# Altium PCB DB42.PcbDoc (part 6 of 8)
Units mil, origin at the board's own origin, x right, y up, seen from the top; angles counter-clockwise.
Board outline 3236.22 x 4456.69 mil, 8 copper layers (Top Layer, MidLayer1, MidLayer2, GND-Layer5, MidLayer3, VCC, MidLayer4, Bottom Layer), stack 62.194 mil thick; 214 components, 470 nets, 1802 pads, 1663 vias.
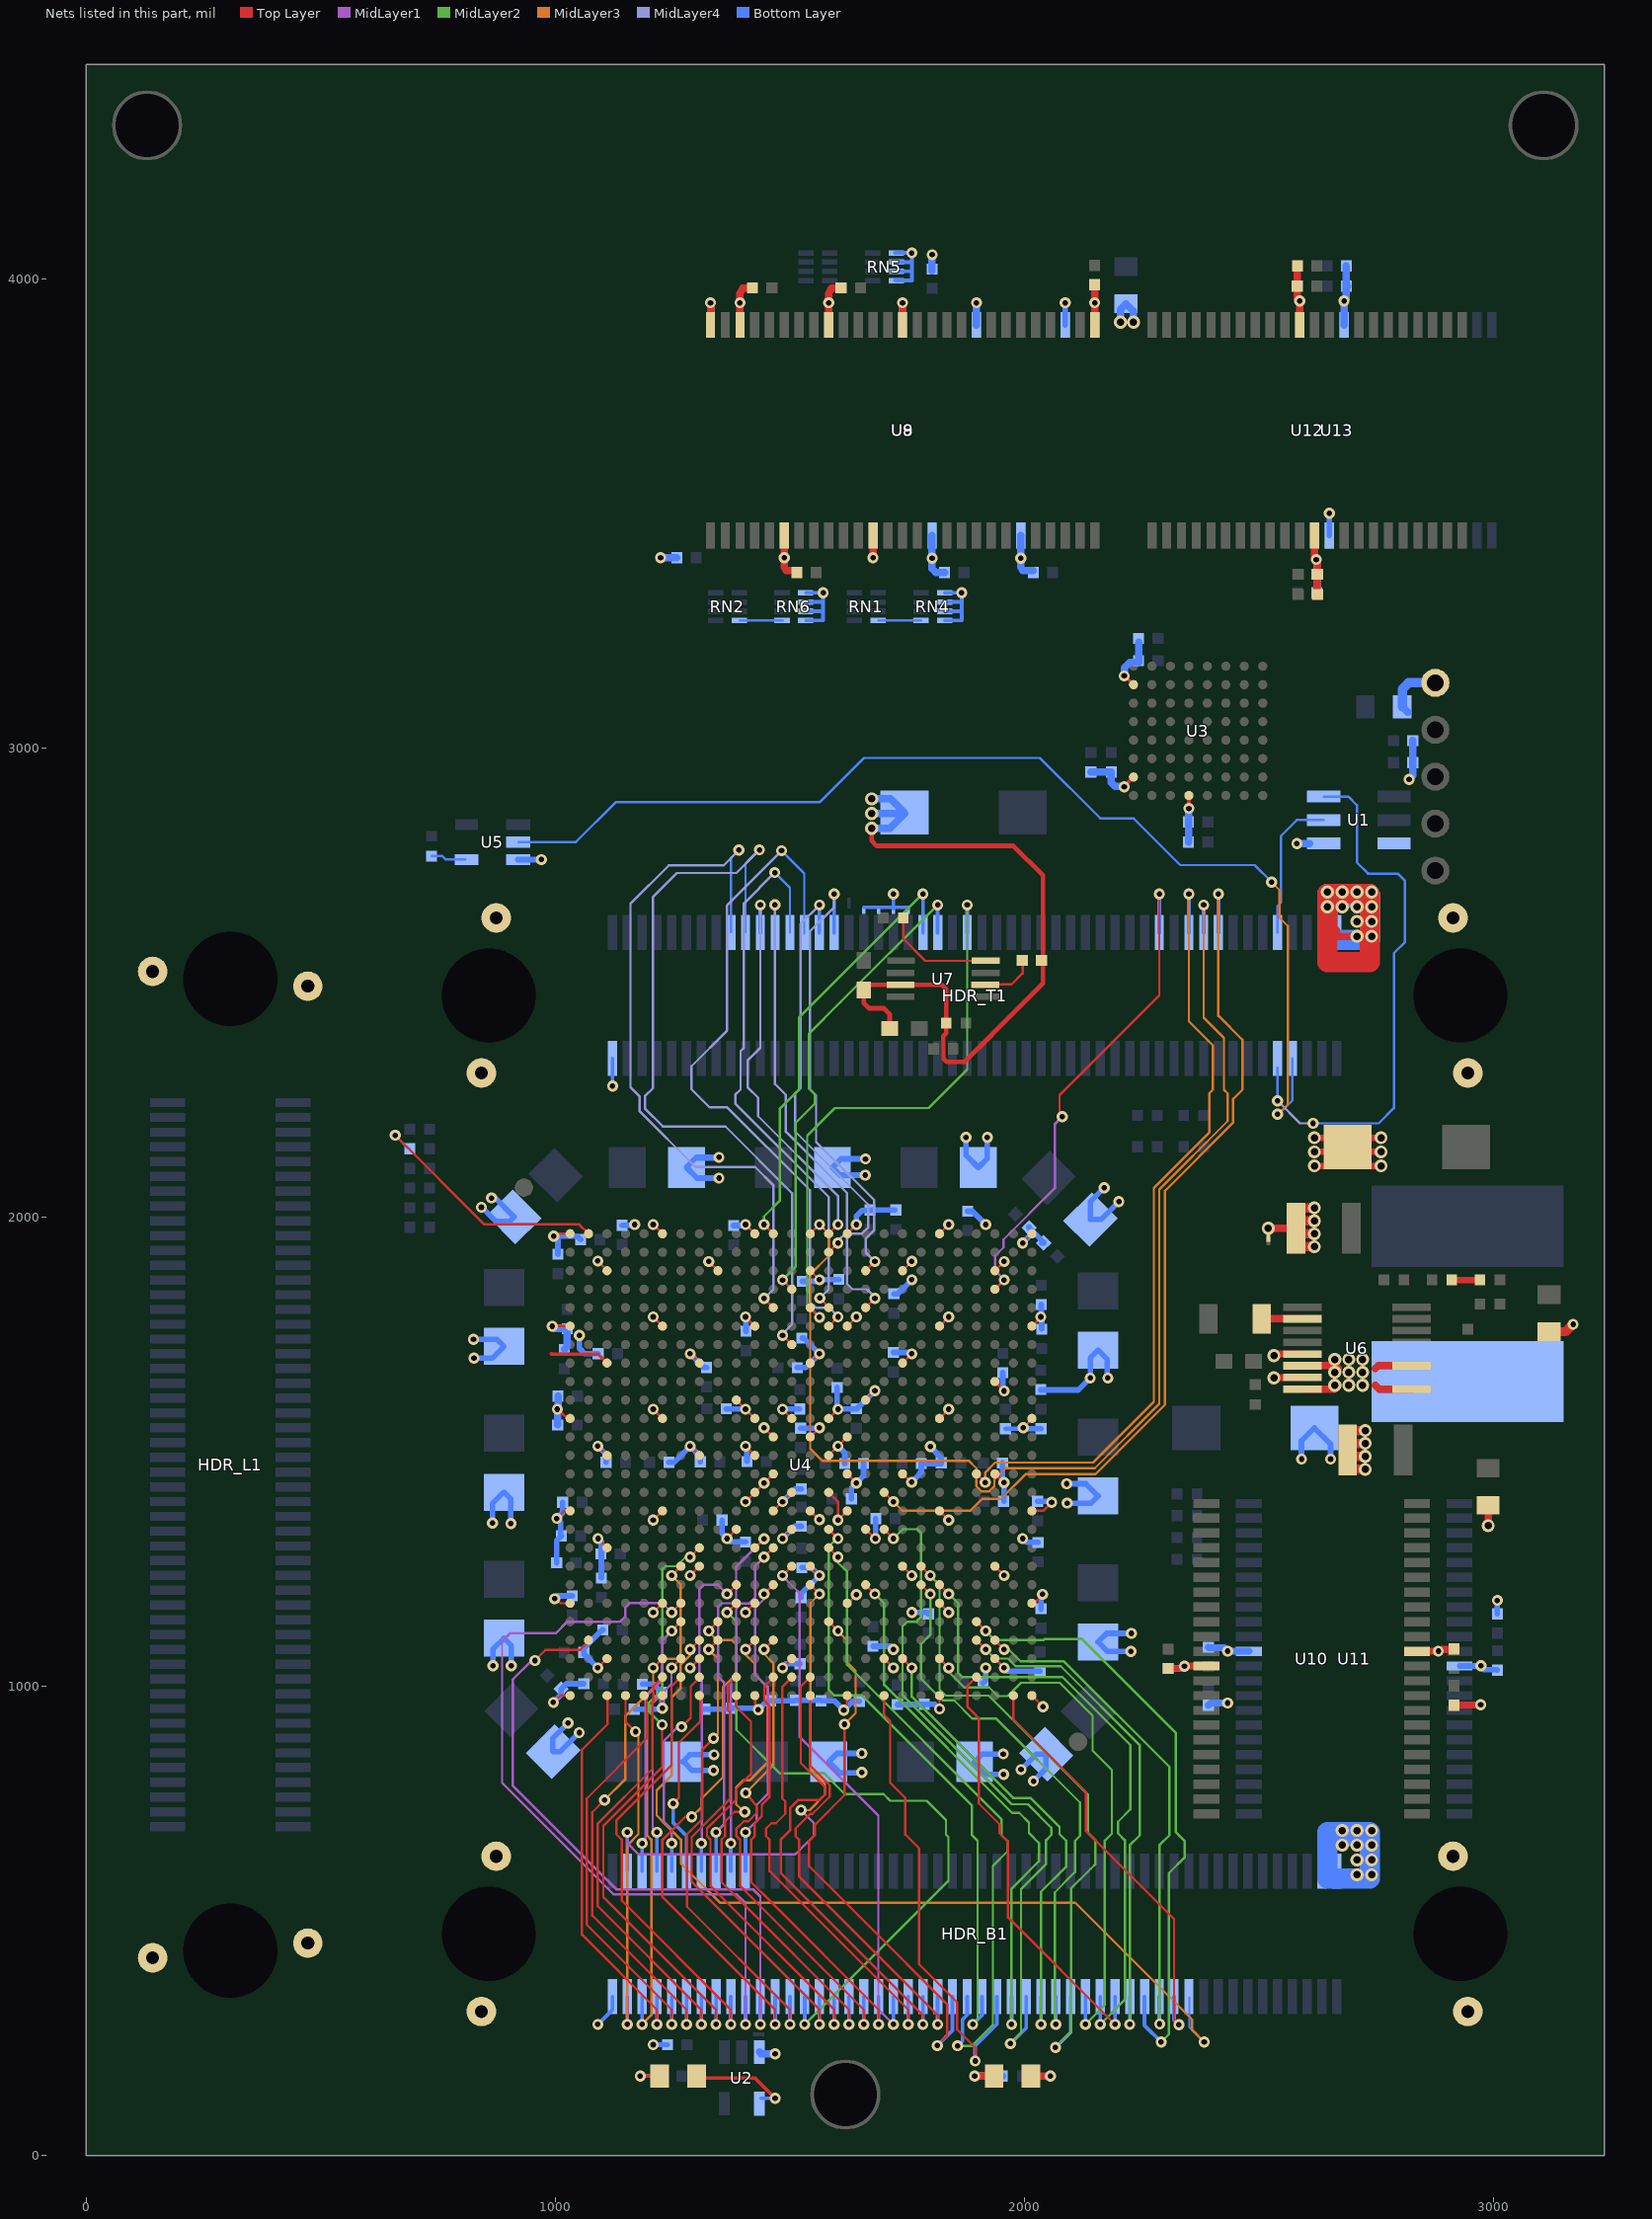
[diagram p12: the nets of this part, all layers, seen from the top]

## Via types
v1: diameter 23.62, hole 11.81, Top Layer to Bottom Layer, 1081 vias
v2: diameter 23.62, hole 11.81, Top Layer to Bottom Layer, tented both sides, 466 vias
v3: diameter 27.56, hole 15.75, Top Layer to Bottom Layer, 116 vias

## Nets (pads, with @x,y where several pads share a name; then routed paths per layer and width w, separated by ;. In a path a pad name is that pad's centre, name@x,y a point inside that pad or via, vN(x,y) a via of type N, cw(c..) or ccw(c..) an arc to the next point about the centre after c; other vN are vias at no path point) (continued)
GND: C1.1 C2.2 C3.2 C4.2 C5.2 C6.2 C7.2 C8.2 C9.2 C10.2 C11.2 C12.2 C13.2 C14.2 C15.2 C16.2 C17.2 C18.2 C19.2 C20.2 C21.2 C22.2 C23.2 C24.2 C25.2 C26.2 C27.2 C28.2 C29.2 C30.2 C31.2 C32.2 C33.2 C34.2 C35.2 C36.2 C37.2 C38.2 C39.2 C40.2 C41.2 C42.2 C43.2 C44.2 C45.2 C46.2 C47.2 C48.2 C49.2 C50.2 C51.2 C52.2 C53.2 C54.2 C55.2 C56.2 C57.2 C58.2 C59.2 C60.2 C61.2 C62.2 C63.2 C64.2 C65.2 C66.2 C67.2 C68.2 C69.2 C70.2 C71.2 C72.2 C73.2 C74.2 C75.2 C76.2 C77.2 C78.2 C79.2 C80.2 C81.2 C82.2 C83.2 C84.2 C85.2 C86.2 C87.2 C88.2 C89.2 C90.2 C91.2 C92.2 C93.2 C94.2 C95.2 C96.2 C97.2 C98.2 C99.2 C100.2 C101.1 C102.2 C103.2 C104.2 C105.2 C106.2 C107.2 C108.2 C109.2 C112.2 C113.2 C114.2 C115.2 C116.2 C118.2 C119.2 C120.2 C121.2 C122.2 C123.2 C124.2 C125.2 C126.2 C127.2 C128.2 C129.2 C130.2 C131.2 C132.2 C133.2 C134.2 C135.2 C136.2 C137.2 C138.2 C139.2 C140.2 C141.2 C142.2 C143.2 C144.2 HDR_B1.1 HDR_B1.98 HDR_B1.100 HDR_B1.MH1 HDR_B1.MH2 HDR_B1.MH3 HDR_B1.MH4 HDR_L1.MH1 HDR_L1.MH2 HDR_L1.MH3 HDR_L1.MH4 HDR_T1.1 HDR_T1.98 HDR_T1.100 HDR_T1.MH1 HDR_T1.MH2 HDR_T1.MH3 HDR_T1.MH4 LED2.2 NT2.2 NT3.2 NT4.2 NT5.2 NT8.2 R25.2 RN4.1 RN4.2 RN4.3 RN4.4 RN5.1 RN5.2 RN5.3 RN5.4 RN6.1 RN6.2 RN6.3 RN6.4 TP1.1 U1.1 U2.3 U3.E8 U3.H2 U3.H7 U4.A1 U4.A6 U4.A11 U4.A16 U4.A21 U4.A26 U4.AA1 U4.AA6 U4.AA11 U4.AA16 U4.AA21 U4.AA26 U4.AD3 U4.AD8 U4.AD13 U4.AD18 U4.AD24 U4.AF1 U4.AF6 U4.AF11 U4.AF16 U4.AF21 U4.AF26 U4.C3 U4.C9 U4.C14 U4.C19 U4.C24 U4.F1 U4.F6 U4.F11 U4.F16 U4.F21 U4.F26 U4.H3 U4.H8 U4.H14 U4.H19 U4.J24 U4.K10 U4.K17 U4.L1 U4.L6 U4.L11 U4.L13 U4.L15 U4.L21 U4.L26 U4.M12 U4.M14 U4.M16 U4.N3 U4.N8 U4.N11 U4.N15 U4.P12 U4.P16 U4.P19 U4.P24 U4.R11 U4.R13 U4.R15 U4.T1 U4.T6 U4.T12 U4.T14 U4.T16 U4.T21 U4.T26 U4.U10 U4.U13 U4.U17 U4.V3 U4.W8 U4.W14 U4.W19 U4.W24 U5.3 U6.13 U6.15 U7.3 U8.6 U8.12 U8.28 U8.41 U8.46 U8.52 U8.54 U9.6 U9.12 U9.28 U9.41 U9.46 U9.52 U9.54 U10.12 U10.34 U11.12 U11.34 U12.12 U12.34 U13.12 U13.34 | length 16704.6
  Top Layer w5: v1(993.19,1767.4) 992.87,1767.72 993.19,1767.72 U4.F1@1031.5,1767.72 ; v1(995.87,965.71) 1011.18,981.02 1031.5,981.02 U4.AF1@1034.8,981.02 ; v1(996.69,1959.45) 1001.81,1964.57 U4.A1@1031.5,1964.57 ; v1@999.29,1189.13 1000.24,1188.18 1011.26,1177.17 U4.AA1@1031.5,1177.17 ; v1(1003.15,1357.87) 1019.29,1374.02 U4.T1@1031.5,1374.02 ; v1(1004.33,1590.55) 1025.31,1571.85 1025.31,1570.87 1025.31,1569.88 U4.L1@1026.3,1570.87 ; v1(1090.55,1039.37) U4.AD3@1110.24,1059.05 ; v1(1090.55,1511.81) U4.N3@1110.24,1492.13 ; v1(1090.59,1906.57) U4.C3@1110.24,1885.83 ; v1(1090.94,1314.96) 1110.24,1295.67 U4.V3@1110.24,1295.28 ; U4.H3@1108.72,1689.87 U4.H3@1109.11,1689.87 ; v1(1208.66,1157.48) U4.AA6@1228.35,1177.17 ; v1(1208.66,1354.33) U4.T6@1228.35,1374.02 ; v1(1208.66,1590.55) U4.L6@1228.35,1570.87 ; v1(1208.66,1787.4) U4.F6@1228.35,1767.72 ; v1(1208.66,1984.25) U4.A6@1228.35,1964.57 ; v1@1226.77,954.33 U4.AF6@1226.77,979.13 ; v1(1227.87,953.54) U4.AF6@1227.87,977.91 ; v1(1287.4,1039.37) U4.AD8@1307.09,1059.05 ; v1(1287.4,1236.22) U4.W8@1307.09,1255.91 ; v1(1287.4,1511.81) U4.N8@1307.09,1492.13 ; v1(1287.4,1708.66) U4.H8@1307.09,1688.98 ; v1(1326.77,1905.51) U4.C9@1346.46,1885.83 ; v1(1366.14,1314.96) U4.U10@1385.83,1334.65 ; U4.K10@1386.61,1610.63 1386.61,1610.24 1386.61,1609.45 v1(1405.51,1590.55) U4.L11@1425.2,1570.87 ; v1(1405.51,1157.48) U4.AA11@1425.2,1177.17 ; v1(1405.51,1393.7) U4.R11@1425.2,1413.39 v1(1444.88,1433.07) U4.P12@1464.57,1452.76 ; v1(1405.51,1511.81) U4.N11@1425.2,1492.13 ; v1(1405.51,1787.4) U4.F11@1425.2,1767.72 ; v1(1405.51,1984.25) U4.A11@1425.2,1964.57 ; U4.AF11@1425.91,979.96 1425.91,957.17 v1(1432.64,950.43) ; v1(1444.88,1551.18) U4.M12@1464.57,1531.5 ; U4.T12@1464.57,1374.02 v1(1484.25,1393.7) U4.R13@1503.94,1413.39 ; v1(1484.25,1039.37) U4.AD13@1503.94,1059.05 ; v1(1484.25,1314.96) U4.U13@1503.94,1334.65 1504.33,1335.04 U4.U13@1505.12,1335.04 ; v1(1484.25,1590.55) U4.L13@1503.94,1570.87 ; U4.W14@1543.31,1255.91 v1(1562.99,1236.22) ; U4.T14@1543.31,1374.02 1562.4,1354.92 v1@1562.99,1354.33 ; U4.M14@1543.31,1531.5 v1(1562.99,1551.18) ; U4.H14@1543.31,1688.98 v1(1562.99,1708.66) ; U4.C14@1543.31,1885.83 1543.7,1885.83 v1(1562.99,1866.54) ; U4.L15@1577.01,1569.88 U4.L15@1580.33,1573.21 ; U4.R15@1582.68,1413.39 1602.36,1393.7 v1(1602.36,1354.33) U4.T16@1622.05,1374.02 ; U4.N15@1582.68,1492.13 v1(1602.36,1511.81) U4.M16@1622.05,1531.5 ; U4.L15@1582.68,1570.87 v1(1602.36,1590.55) ; v1(1614.84,949.37) 1622.05,956.57 U4.AF16@1622.05,980.31 ; U4.AA16@1622.05,1177.17 1623.62,1177.16 v1(1641.73,1195.28) ; U4.P16@1622.05,1452.76 v1(1641.73,1433.07) ; U4.F16@1622.05,1767.72 v1(1641.73,1787.4) ; U4.A16@1622.05,1964.57 v1(1641.73,1984.25) ; U4.U17@1661.42,1334.65 v1(1682.28,1314.96) ; U4.K17@1661.42,1610.24 v1(1681.1,1629.92) ; U4.AD18@1700.79,1059.05 v1(1720.47,1039.37) ; U4.W19@1740.16,1255.91 v1(1759.84,1236.22) ; U4.P19@1740.16,1452.76 v1(1759.45,1435.04) ; U4.H19@1740.16,1688.98 v1(1759.84,1708.66) ; U4.C19@1740.16,1885.83 v1(1759.84,1905.91) ; U4.AF21@1818.9,980.31 1818.9,951.93 v1(1819.09,951.73) ; U4.AA21@1818.9,1177.17 v1(1838.58,1157.48) ; U4.T21@1818.9,1374.02 v1(1838.58,1354.33) ; U4.L21@1818.9,1570.87 v1(1838.58,1590.55) ; U4.F21@1818.9,1767.72 v1(1838.58,1787.4) ; U4.A21@1818.9,1964.57 v1(1838.58,1984.25) ; U4.AD24@1937.01,1059.05 v1(1956.69,1039.37) ; U4.W24@1937.01,1255.91 v1(1956.69,1236.22) ; U4.P24@1937.01,1452.76 1956.1,1434.05 v1@1956.3,1433.86 ; U4.J24@1937.01,1649.61 1937.01,1649.21 v1(1956.69,1629.53) ; U4.C24@1937.01,1885.83 v1(1956.69,1905.51) ; v1@1997.19,1946.36 2015.39,1964.57 U4.A26@2015.75,1964.57 U4.A26@2016.54,1964.57 ; v1(1997.24,1551.18) 2015.75,1569.69 U4.L26@2015.75,1570.87 ; U4.AF26@2015.75,980.31 v1(2039.41,956.65) ; U4.AA26@2015.75,1177.17 2020.47,1177.17 v1@2037.8,1194.49 ; U4.T26@2015.75,1374.02 2039.76,1374.02 v1(2057.87,1392.13) ; U4.F26@2015.75,1767.72 2016.14,1767.72 v1@2032.68,1784.25
  Top Layer w7.87: v1@2212.6,2918.31 U3.H7@2232.28,2937.99 ; v1@2212.6,3154.53 2213.09,3154.04 U3.H2@2232.28,3134.84 ; v1(2350.4,2871.07) U3.E8@2350.39,2898.62
  Top Layer w8: 992.13,1708.66 992.97,1707.82 1091.39,1707.82 U4.H3@1110.24,1688.98 ; 1826.77,2377.95 1827.63,2377.09 1827.63,2337.72 1830.71,2334.65 ; 1875.2,2331.89 1930.31,2387
  Top Layer w10: C119.2@1657.48,2484.25 1657.48,2456.7 1669.29,2444.88 1700.79,2444.88 1712.59,2433.07 C118.2@1712.59,2409.44 ; C119.2@1657.48,2495.07 U7.3@1736.22,2495.07 1823.82,2495.07 1833.15,2485.75 R25.2@1833.15,2413.38 1833.15,2392.2 1826.77,2385.83 1826.77,2377.95 ; v3(1674.21,2828.74) 1674.21,2802.16 1685.04,2791.33 1976.37,2791.33 2039.37,2728.34 2039.37,2547.24 2039.37,2498.03 2016.63,2475.29 ; 1828.68,2336.67 1834.25,2331.1 1872.44,2331.1 2036.41,2495.07
  Top Layer w12: C130.2@2306.5,1038.11 2336.11,1038.11 v1(2341,1043)
  Top Layer w13.78: v3(2618.11,2109.29) C99.2@2669.08,2109.29 ; v3(2618.11,2139.29) C99.2@2669.08,2139.29 ; v3(2618.11,2169.29) C99.2@2669.08,2169.29 ; C99.2@2709.01,2109.29 v3(2759.99,2109.29) ; C99.2@2709.01,2139.29 v3(2759.99,2139.29) ; C99.2@2709.01,2169.29 v3(2759.99,2169.29)
  Top Layer w15: v1@2341,1041.79 v1(2341,1043) 2341.3,1043.3 U10.34@2387.89,1043.3 ; v3(2531.5,1657.48) 2532.26,1658.25 U6.15@2591.08,1658.25 ; v3(2531.5,1704.72) 2535.43,1708.66 U6.13@2590.55,1708.66 ; U10.12@2836.71,1074.8 2881.8,1074.8 v1(2882,1075) 2886.02,1075 2889.76,1078.74 2914.47,1078.74 C129.2@2915.44,1079.71 ; C131.2@2915.31,957.92 2917.32,957.76 C131.2@2915.44,959.64 2914.45,960.63 2915.44,960.63 v1(2972.44,960.63)
  Top Layer w15.75: U8.54@1330.71,3901.57 v2(1330.71,3948.82) ; U8.52@1393.7,3901.57 v2(1393.7,3948.82) ; v2@1393.7,3944.88 v2(1393.7,3948.82) ; 1393.7,3964.57 v2(1393.7,3948.82) ; 1393.7,3968.51 1399.61,3980.32 C125.2@1416.34,3980.32 ; C125.2@1418.31,3978.34 C125.2@1416.34,3980.32 ; C125.2@1420.27,3980.31 C125.2@1416.34,3980.32 ; U8.6@1488.19,3452.76 1488.19,3409.45 v2(1488.19,3405.51) 1488.19,3385.83 1492.13,3377.95 C122.2@1514.76,3377.95 ; U8.46@1582.68,3901.57 v2(1582.68,3948.82) ; v2@1582.68,3944.88 v2(1582.68,3948.82) ; C126.2@1609.25,3980.31 1588.58,3980.32 1582.68,3968.51 1582.68,3964.57 v2(1582.68,3948.82) ; v2(1677.17,3405.51) U8.12@1677.17,3452.76 ; U8.41@1740.16,3901.57 v2(1740.16,3948.82) ; LED2.2@2011.81,169.29 LED2.2@2013.78,169.29 v1(2055.12,169.29) ; U8.28@2149.61,3901.57 v2(2149.61,3948.82) C121.2@2149.6,3987.2 ; v3(2519.68,1976.38) 2578.74,1976.38 C116.2@2582.67,1976.38 ; C138.2@2580.43,4028.54 C138.2@2580.57,4028.67 ; C138.2@2581.69,4027.55 2581.69,3984.24 2581.69,3957.68 v2(2586.61,3952.76) U12.34@2586.61,3901.57 ; U12.12@2618.11,3452.76 2618.11,3405.51 v2(2622.05,3401.57) 2624.72,3398.9 C141.2@2624.72,3370.07 C141.2@2625.71,3371.06 ; C137.2@2623.74,3329.72 2623.74,3370.07 C141.2@2623.77,3370.23 ; 2645.67,2598.43 v3(2708.66,2598.43) ; v3(2988.19,1342.52) C113.2@2988.18,1385.82
  Top Layer w19.68: C115.2@3118.1,1755.9 3153.54,1755.9 v1(3169.29,1771.65)
  Top Layer w20: C116.2@2578.74,1937 v3(2618.1,1937) ; C116.2@2578.74,1964.56 v3(2618.1,1964.56) ; C116.2@2578.74,1992.12 v3(2618.1,1992.12) ; C116.2@2578.74,2019.68 v3(2618.1,2019.68) ; C114.2@2687.01,1462.59 2688.97,1462.59 v3(2726.38,1462.59) ; C114.2@2687.01,1490.15 2688.97,1490.15 v3(2726.38,1490.15) ; C114.2@2687.01,1517.71 2688.97,1517.71 v3(2726.38,1517.71) ; C114.2@2687.01,1545.27 2688.97,1545.27 v3(2726.38,1545.27)
  Top Layer w39.37: 2645.67,2606.3 2653.54,2606.3
  Top Layer w43.31: 2645.67,2543.31 2736.22,2543.31 2736.22,2598.43 2736.22,2629.92 2736.22,2661.42 2736.22,2688.98 2708.66,2688.98 2677.17,2688.98 2645.67,2688.98 v3(2645.67,2661.42) 2645.67,2606.3 2645.67,2598.43 2645.67,2543.31
  Bottom Layer w5: v1@1003.15,1350.39 v1(1003.15,1357.87) ; v1@1223.23,958.66 1227.56,954.33 1228.11,953.78 v1@1228.74,953.15
  Bottom Layer w7.87: v2(1090.55,279.53) 1122.05,311.02 HDR_B1.1@1122.05,338.58 ; v2(1122.05,2279.53) HDR_T1.1@1122.05,2338.58 ; RN6.4@1534.64,3271.65 1570.87,3271.65 1570.87,3291.34 ; RN6.3@1534.64,3291.34 1570.87,3291.34 ; RN6.2@1534.64,3311.02 1570.87,3311.02 ; RN6.1@1534.64,3330.71 v1(1570.87,3330.71) 1570.87,3311.02 ; NT5.2@1657.48,2660.43 1688.97,2660.43 NT3.2@1720.47,2660.43 ; NT3.2@1720.47,2657.48 NT3.2@1720.47,2660.43 ; v2(1720.47,2688.98) NT3.2@1720.47,2660.43 ; RN5.4@1723.62,3996.06 RN5.4@1726.58,3996.06 1759.84,3996.06 1759.84,4015.75 ; RN5.3@1723.62,4015.75 RN5.3@1726.58,4015.75 1759.84,4015.75 ; RN5.2@1723.62,4035.43 RN5.2@1726.58,4035.43 1759.84,4035.43 ; RN5.1@1723.62,4055.12 RN5.1@1726.58,4055.12 v1(1759.84,4055.12) 1759.84,4035.43 ; NT2.2@1751.96,2660.43 NT3.2@1720.47,2660.43 ; RN4.4@1829.93,3271.65 1866.14,3271.65 1866.14,3291.34 ; RN4.3@1829.93,3291.33 1866.14,3291.34 ; RN4.2@1829.93,3311.02 1866.14,3311.02 ; RN4.1@1829.93,3330.7 v1(1866.14,3330.71) 1866.14,3311.02 ; 1570.87,3291.34 1570.87,3311.02 ; 1759.84,4015.75 1759.84,4035.43 ; 1866.14,3291.34 1866.14,3311.02
  Bottom Layer w9.84: v1(1208.66,236.22) C101.1@1239.17,236.22
  Bottom Layer w10: C75.2@1959.65,1549.21 1994.88,1549.21 v1@1996.06,1550.39
  Bottom Layer w11.81: v1(825.58,1739.71) 875.11,1739.71 C10.2@890.44,1724.38 865.43,1699.37 v1(826.56,1699.37) ; v1(865.92,1348.08) 865.92,1389.41 889.95,1413.44 C42.2@890.44,1413.44 891.09,1413.44 905.28,1399.25 v1(905.28,1347.1) ; v1(866.9,1044.02) 866.9,1078.91 C8.2@890.44,1102.45 906.26,1086.63 v1(906.26,1044.02) ; C20.2@994.82,861.98 994.82,889.54 v1(1027.3,922.01) ; C20.2@995.54,860.94 1010.51,860.94 v1(1050.91,901.34) ; v1(1004.33,1590.55) v1@1004.92,1591.14 ; v1(1090.55,1511.81) 1108.27,1494.09 C44.2@1108.27,1477.36 ; v1@1227.56,954.33 C66.2@1227.56,986.61 ; C46.2@1242.13,1477.36 1252.95,1477.36 v1(1287.4,1511.81) 1309.06,1490.16 C30.2@1309.06,1478.35 ; C9.2@1271.74,839.26 C9.2@1272.59,840.11 ; v1(1337.26,820.66) 1292.05,820.66 C9.2@1272.59,840.11 ; v1(1338.24,854.11) 1286.59,854.11 C9.2@1272.59,840.11 ; C71.2@1355.31,1354.33 1355.31,1325.79 v1(1366.14,1314.96) 1373.42,1307.68 C49.2@1405.51,1307.68 ; C77.2@1364.17,1591.54 1404.53,1591.54 v1(1405.51,1590.55) ; v1@1405.12,1512.99 1405.9,1512.21 v1@1406.5,1511.61 ; v1(1405.51,1511.81) 1408.46,1508.86 C17.2@1408.46,1479.33 ; v1(1405.51,1787.4) 1406.5,1786.42 C78.2@1406.5,1756.89 ; v1@1483.07,1039.76 1483.46,1040.16 1491.54,1048.23 C52.2@1521.65,1048.23 ; v1(1484.25,1393.7) v1@1485.24,1394.68 ; C45.2@1515.75,1679.13 1533.46,1679.13 v1(1562.99,1708.66) 1529.53,1742.13 C51.2@1525.59,1742.13 ; C15.2@1522.64,1550.2 1562.01,1550.2 v1(1562.99,1551.18) ; C53.2@1523.62,1188.98 1523.62,1196.85 v1(1562.99,1236.22) 1546.26,1252.95 C27.2@1525.59,1252.95 ; v1@1559.65,1863.19 v1(1562.99,1866.54) v1@1563.58,1867.13 ; v1@1599.41,1508.86 v1(1602.36,1511.81) ; C70.2@1600.39,1636.81 1600.39,1594.09 v1@1602.95,1591.54 ; v1@1601.57,1590.16 1602.17,1590.75 v1@1602.95,1591.54 ; v1@1603.15,1591.34 v1@1602.95,1591.54 ; C12.2@1630.91,1399.61 1630.91,1422.24 v1(1641.73,1433.07) ; v1(1641.73,1984.25) 1641.73,2001.88 1654.1,2014.25 1669.84,2014.25 C96.2@1670.83,2015.24 ; v1(1653.12,816.72) 1652.14,815.74 1606.25,815.74 C39.2@1582.72,839.26 1600.52,857.06 v1(1653.12,857.06) ; v1(1681.1,1629.92) 1642.72,1591.54 C18.2@1641.73,1591.54 v1@1602.95,1591.54 ; v1(1682.28,1314.96) 1683.07,1316.93 C76.2@1683.07,1357.28 ; C86.2@1786.42,961.61 1809.21,961.61 v1(1819.09,951.73) ; v1(1799.61,1511.02) 1822.83,1486.61 C50.2@1822.83,1476.38 ; v1(1875.5,2169.72) 1875.5,2131.76 C5.2@1901.55,2105.71 1920.77,2124.93 v1(1920.77,2169.72) ; v1(1954.72,855.91) 1910.31,855.91 C7.2@1893.67,839.26 1920.34,812.6 v1(1955.51,812.6) ; v1@1955.82,1432.98 1956.6,1432.19 1956.6,1394.33 C28.2@1956.6,1393.97 ; v1(1956.3,1434.25) v1@1958.07,1436.02 ; v1(1992.6,822.62) 2025.35,855.37 C19.2@2046.14,855.37 2046.14,825 v1(2019.17,798.02) ; v1@1998.03,1549.61 1998.42,1549.21 C67.2@2035.43,1549.21 ; v1@2034.25,1788.98 2034.45,1788.78 v1@2034.45,1787.4 ; C89.2@2035.43,1164.37 C89.2@2035.43,1165.35 2035.43,1192.13 v1@2038.58,1195.28 ; v1@2038.19,1197.64 2039.07,1196.75 v1@2042.52,1193.31 ; U9.52@2086.61,3901.57 v2(2086.61,3948.82) ; v1(2090.02,1431.72) 2130.74,1431.72 C40.2@2156.9,1405.56 2141.73,1390.39 v1(2091,1390.39) ; v1(2140.2,1657.06) 2140.2,1699.84 C3.2@2156.88,1716.52 2176.61,1696.79 v1@2176.61,1658.04 ; U9.54@2149.61,3901.57 v2(2149.61,3948.82) ; v1(2169.72,2062.46) 2140.79,2033.53 C21.2@2140.79,1994.88 2163.14,1994.88 v1(2201.21,2032.94) ; v1(2226.79,1074.53) 2176.94,1074.53 C4.2@2156.9,1094.57 2175.23,1112.9 v1(2227.78,1112.9) ; U13.12@2649.61,3452.76 v2(2649.61,3500) ; U11.34@2927.25,1043.3 v1@2972.3,1043.3 ; v1(2973,1044) v1@2972.3,1043.3 ; C136.2@3007.87,1034.44 3006.88,1035.43 2979.33,1035.43 2972.3,1042.47 v1@2972.3,1043.3 ; C134.2@3007.87,1154.52 v1(3007.87,1183.07)
  Bottom Layer w12: v2(842.3,2021.14) 843.29,2021.14 873.79,1990.63 902.21,1990.63 C22.2@912.02,2000.45 871.65,2040.82 v2(863.95,2040.82) ; U5.3@920.04,2762.09 v1(970.22,2762.09) ; v1(995.87,965.71) 1012.39,982.23 C35.2@1012.39,993.98 1024.05,1005.65 C92.2@1060.75,1005.65 ; v1(998.79,1186.73) 1004.68,1192.61 C60.2@1036.15,1192.61 ; C98.2@1002.69,1263.46 1002.69,1310.76 C57.2@1012.8,1320.87 C57.2@1013.51,1320.15 ; C65.2@1005.65,1920.77 1005.65,1950.49 v1(996.69,1959.45) 1046.67,1959.45 C14.2@1053.86,1952.26 ; C57.2@1011.79,1320.29 1011.4,1320.69 1011.4,1320.87 1011.4,1349.63 v1(1003.15,1357.87) 1015.48,1370.21 C69.2@1015.48,1392.36 ; v1(1051.18,1748.03) 1051.18,1720.47 1062.45,1709.21 C94.2@1091.25,1709.21 C94.2@1089.77,1709.21 ; v1(1090.55,1039.37) 1060.76,1069.16 C83.2@1060.76,1072.56 1060.76,1081.21 1099.63,1120.08 C25.2@1101.38,1120.08 ; v1(1090.94,1314.96) 1098.14,1307.76 1098.14,1282.15 C73.2@1098.14,1230.99 ; C63.2@1142.42,1982.77 v1@1166.04,1982.76 ; C32.2@1168.01,951.53 1224.76,951.53 1227.32,954.09 v1@1227.56,954.33 ; C84.2@1185.73,1004.66 1209.51,1004.66 C66.2@1226.97,987.2 C66.2@1227.56,986.61 ; v1(1287.4,1708.66) 1316.37,1679.69 C48.2@1322.5,1679.69 ; C91.2@1318.56,951.52 1372.68,951.52 C90.2@1374.65,953.49 1429.58,953.49 v1(1432.64,950.43) 1451.44,969.23 C47.2@1459.27,969.23 1510.44,969.23 C82.2@1511.42,970.22 1565.54,970.22 C61.2@1566.53,969.23 1594.98,969.23 v1(1614.84,949.37) 1633.72,968.25 C80.2@1648.2,968.25 ; v1(1348.82,2083.07) 1302.26,2083.07 C6.2@1279.61,2105.72 1279.62,2106.39 C6.2@1299.21,2125.98 ; C97.2@1379.92,1982.28 1403.54,1982.28 v1(1405.51,1984.25) ; v1(1484.25,1314.96) 1510.48,1341.19 C16.2@1524.22,1341.19 ; v1(1484.25,1393.7) 1511.44,1420.89 C13.2@1524.22,1420.89 ; v1(1484.25,1590.55) 1484.83,1591.13 C37.2@1520.28,1591.13 ; C79.2@1526.57,1863.19 1559.65,1863.19 v1(1562.99,1866.54) ; v1@1562.99,1866.14 v1(1562.99,1866.54) ; v1(1602.36,1511.81) 1616.72,1497.46 C11.2@1616.72,1475.02 ; C41.2@1603.54,2092.52 1590.58,2105.48 C41.2@1590.58,2105.71 C41.2@1590.75,2105.71 ; C26.2@1604.33,1867.13 v1@1563.58,1867.13 ; v1@1642.3,1433.69 1657.05,1448.44 C29.2@1657.05,1475.02 ; v1@1657.48,2092.52 v1(1660.63,2089.37) 1607.09,2089.37 C41.2@1590.75,2105.71 ; v1(1661.02,2124.02) 1609.06,2124.02 C41.2@1590.75,2105.71 ; C96.2@1671.31,2014.76 C96.2@1670.83,2015.24 C81.2@1723.96,2015.24 ; C33.2@1677.17,1085.63 1713.58,1085.63 v1(1720.47,1078.74) ; C24.2@1720.47,1711.61 1756.89,1711.61 v1(1759.84,1708.66) ; C56.2@1721.46,1836.61 1729.92,1836.61 v1(1759.84,1866.54) ; C95.2@1728.89,961.36 1786.17,961.36 C86.2@1786.42,961.61 ; v1(1759.45,1435.04) 1780.06,1455.65 C23.2@1780.06,1475.02 C50.2@1822.37,1475.02 ; v1(1759.84,1157.48) 1792.32,1157.48 C54.2@1795.28,1154.53 ; C64.2@1878.94,2012.8 1888.78,2012.8 v1(1917.32,1984.25) ; C55.2@1911.42,1006.89 1917.32,1012.8 v1(1917.32,1039.37) ; C43.2@1953.25,1476 1953.25,1437.31 v1(1956.3,1434.25) ; C34.2@1953.74,1668.31 1953.74,1632.48 v1(1956.69,1629.53) ; v1(1956.69,1039.37) 1963.85,1032.21 C93.2@2032.94,1032.21 ; v1(1996.06,1314.96) 2004.27,1306.76 C38.2@2029.01,1306.76 ; v1(1996.06,1944.88) 2015.75,1964.57 ; C31.2@2008.84,1978.33 C31.2@2009.33,1978.82 ; C31.2@2010.17,1977 2040.96,1946.21 C74.2@2040.96,1945.22 C74.2@2037.02,1945.22 ; C88.2@2028.02,1394.33 2055.67,1394.33 v1(2057.87,1392.13) ; C58.2@2033.93,1631.47 2034.91,1631.47 2114.62,1631.47 v1(2140.2,1657.06) ; C87.2@2035.9,1813.51 2035.9,1788.65 v1(2034.65,1787.4) ; C36.2@2036.88,1761.37 2036.88,1785.17 v1(2034.65,1787.4) ; v1@2039.37,1787.4 v1(2034.65,1787.4) ; C132.2@2306.5,1038.11 2336.11,1038.11 v1(2341,1043) ; v1(2590.55,1484.25) 2590.55,1523.43 C112.2@2618.04,1550.91 2652.34,1516.61 v1(2652.34,1484.25) ; C6.2@1299.21,2125.98 1300.79,2127.56 v1(1348.82,2127.56) 1347.24,2125.98 C6.2@1299.21,2125.98 ; v1(1562.99,1866.54) v1@1563.58,1867.13 ; v1(1562.99,1866.54) v1@1563.58,1867.13
  Bottom Layer w15: C133.2@2391.82,959.64 2396.75,964.57 v1(2433.07,964.57) ; C135.2@2391.82,1083.65 2392.8,1082.68 2425.2,1082.68 2432.87,1075 v1(2433,1075) 2433.21,1074.79 U11.12@2478.44,1074.79
  Bottom Layer w15.75: v1(993.19,1767.4) 998.25,1762.34 C85.2@1025.33,1762.34 1025.33,1723.97 C68.2@1019.42,1718.07 ; C62.2@1004.92,1557.09 1004.92,1590.55 1004.92,1592.24 1005.64,1592.97 C72.2@1005.64,1618.68 ; v2(1224.41,3405.51) C123.2@1258.85,3405.51 ; U9.28@1330.71,3901.57 v2@1330.71,3944.88 ; U2.3@1435.04,220.47 1438.97,216.54 v1(1468.5,216.54) ; v3(1674.21,2828.74) 1713.39,2828.74 C100.2@1744.88,2860.24 ; v3(1674.21,2860.24) 1744.17,2860.24 C100.2@1744.88,2860.24 ; v3(1674.21,2891.73) 1713.93,2891.73 1743.68,2861.98 1745.15,2860.51 C100.2@1744.88,2860.24 ; U9.41@1740.16,3901.57 v2(1740.16,3948.82) ; U9.12@1803.15,3452.76 1803.15,3405.51 v2(1803.15,3404.53) 1803.15,3381.89 1811.04,3374.01 C128.2@1829.72,3374.01 ; C124.2@1803.15,4016.72 C124.2@1803.15,4020.66 1803.15,4047.24 v2(1803.15,4051.18) ; U9.46@1897.64,3901.57 v2(1897.64,3948.82) v2@1897.64,3944.88 ; U9.6@1992.13,3452.76 v2(1992.13,3404.53) 1992.13,3385.83 1996.06,3377.95 C127.2@2018.7,3377.95 ; C107.2@2141.73,2948.82 C104.2@2185.04,2948.82 2185.04,2926.19 2192.92,2918.31 v1@2212.6,2918.31 ; v3(2204.72,3907.48) 2204.72,3935.04 C109.2@2216.53,3946.84 2232.28,3931.1 v3(2232.28,3907.48) ; v1(2212.6,3153.54) 2212.6,3170.28 2224.41,3182.09 2243.1,3182.09 C106.2@2243.11,3186.02 C103.2@2243.11,3225.39 ; C102.2@2349.41,2799.21 2350.4,2800.2 2350.4,2842.52 v1(2350.4,2871.07) ; v2(2580.71,2796.26) 2608.06,2796.26 U1.1@2608.25,2796.45 ; v2(2622.05,3401.57) 2623.03,3400.6 C143.2@2623.03,3370.07 C139.2@2623.03,3330.7 ; v2@2681.1,3956.7 v2(2681.1,3952.76) 2686.02,3957.67 C144.2@2686.02,3984.24 ; U13.34@2681.38,3901.57 v2@2681.38,3944.88 ; C140.2@2686.02,4027.56 2686.02,3987.2 2687.5,3985.72 C144.2@2688.98,3984.25 ; C108.2@2805.13,3087.59 C108.2@2816.93,3075.79 ; v1(2819.68,2933.07) 2827.75,2941.14 C2.2@2827.75,2968.5 C1.1@2827.75,3015.74
  Bottom Layer w20: C108.2@2805.13,3087.59 2805.12,3125.12 2818.67,3138.67 TP1.1@2875.71,3138.67
  Bottom Layer w43.31: 2649.61,681.1 2677.17,681.1 2708.66,681.1 v3@2736.22,681.1 ; v3@2649.61,2681.1 2677.17,2681.1 2708.66,2681.1 v3@2736.22,2681.1 ; v3@2736.22,681.1 2736.22,688.98 2708.66,688.98 2677.17,688.98 2645.67,688.98 2645.67,661.42 2645.67,606.3 2645.67,590.55 2665.36,590.55 2708.66,590.55 2736.22,590.55 2736.22,598.42 2736.22,629.92 2736.22,661.42 v3@2736.22,681.1 ; v3@2736.22,2681.1 2736.22,2688.98 2708.66,2688.98 2677.17,2688.98 2645.67,2688.98 v3(2645.67,2661.42) 2645.67,2606.3 2645.67,2590.55 2665.36,2590.55 2708.66,2590.55 2736.22,2590.55 2736.22,2598.43 2736.22,2629.92 2736.22,2661.42 v3@2736.22,2681.1
  other v1: 2038.58,1196.26 1562.99,1355.51 2177.59,1657.06 1169.29,1984.25 2212.6,2917.32
  other v3: 2708.66,598.42 2740.16,598.42 2708.66,629.92 2740.16,629.92 2677.17,661.42 2708.66,661.42 2740.16,661.42 2677.17,692.91 2708.66,692.91 2740.16,692.91 2740.16,2598.43 2708.66,2629.92 2740.16,2629.92 2677.17,2661.42 2708.66,2661.42 2740.16,2661.42 2645.67,2692.91 2677.17,2692.91 2708.66,2692.91 2740.16,2692.91
IO0: HDR_B1.7 U4.AF3 | length 849
  Top Layer w5: U4.AF3@1110.75,979.66 1110.75,980.31 U4.AF3@1110.75,980.75 ; U4.AF3@1111.4,979.66 1111.4,919.52 1056.93,865.05 1056.93,470.63 1216.54,311.02 v2(1216.54,279.53)
  Bottom Layer w7.87: v2(1216.54,279.53) HDR_B1.7@1216.54,338.58
IO1: HDR_B1.9 U4.AF5 | length 888.5
  Top Layer w5: 1066.93,700 1066.93,492.13 1248.03,311.02 v2(1248.03,279.53) ; 1066.93,701.57 1066.93,760.91 1194.58,888.55 1194.58,974.91 U4.AF5@1189.13,980.35
  Bottom Layer w7.87: v2(1248.03,279.53) HDR_B1.9@1248.03,338.58
IO2: HDR_B1.11 U4.AD6 | length 983.7
  Top Layer w5: v1(1105.12,757.87) 1078.74,731.5 1078.74,511.81 1279.53,311.02 v2(1279.53,279.53) ; v1(1208.66,1039.37) U4.AD6@1228.35,1059.05
  MidLayer3 w5: v1(1105.12,757.87) 1148.8,801.55 1148.8,936.27 1208.66,996.13 v1(1208.66,1039.37)
  Bottom Layer w7.87: v2(1279.53,279.53) HDR_B1.11@1279.53,338.58
IO3: HDR_B1.13 U4.AE6 | length 947.6
  Top Layer w5: U4.AE6@1228.35,1019.68 1209.09,1000.43 1209.09,965 1207,962.91 1207,824 1090.55,707.55 1090.55,531.5 1311.02,311.02 v2(1311.02,279.53)
  Bottom Layer w7.87: v2(1311.02,279.53) HDR_B1.13@1311.02,338.58
IO4: HDR_B1.15 U4.V8 | length 1301.5
  Top Layer w5: v1(1227.56,918.11) 1227.56,827.56 1102.36,702.36 1102.36,551.18 1342.52,311.02 v2(1342.52,279.53) ; v1(1287.4,1275.59) U4.V8@1307.09,1295.28
  MidLayer2 w5: v1(1227.56,918.11) 1200,945.67 1200,965.35 1228.35,993.7 1228.35,1250 1234.25,1255.91 1257.87,1255.91 1277.56,1275.59 v1(1287.4,1275.59)
  Bottom Layer w7.87: v2(1342.52,279.53) HDR_B1.15@1342.52,338.58
IO5: HDR_B1.17 U4.AE7 | length 957.4
  Top Layer w5: U4.AE7@1267.72,1019.68 1247.64,999.61 1247.64,831.64 1129.92,713.92 1129.92,685.04 1141.73,673.23 1141.73,543.31 1374.02,311.02 v2(1374.02,279.53)
  Bottom Layer w7.87: v2(1374.02,279.53) HDR_B1.17@1374.02,338.58
IO6: HDR_B1.19 U4.AA7 | length 1687.6
  Top Layer w5: v1(1248.03,1157.48) U4.AA7@1267.72,1177.17
  MidLayer1 w5: v1@1248.03,1157.09 v1(1248.03,1157.48) 1227.97,1177.54 1158.36,1177.54 1149.3,1168.48 1149.3,1148.9 1138.2,1137.81 1025.52,1137.81 1000.71,1113 903.41,1113 886.58,1096.18 886.58,794.42 1124.16,556.84 1386.71,556.84 1405.51,538.04 v2(1405.51,279.53)
  Bottom Layer w7.87: v2(1405.51,279.53) HDR_B1.19@1405.51,338.58
IO7: HDR_B1.21 U4.AC2 | length 1381.6
  Top Layer w5: v1(956.45,1054.85) 979.04,1077.44 1053.19,1077.44 1070.87,1095.12 U4.AC2@1070.87,1098.42
  MidLayer1 w5: v1(956.45,1054.85) 949.56,1054.85 909,1014.29 909,789 1131.07,566.93 1422.07,566.93 1437.01,551.99 v2(1437.01,279.53)
  Bottom Layer w7.87: v2(1437.01,279.53) HDR_B1.21@1437.01,338.58
IO8: HDR_B1.23 U4.AB9 | length 1141.9
  Top Layer w5: v1(1290.94,722.05) 1277.17,722.05 1228.35,673.23 1228.35,551.18 1468.5,311.02 v2(1468.5,279.53) ; v1(1326.77,1118.11) U4.AB9@1346.46,1137.8
  MidLayer3 w5: v1@1292.43,723.53 v1(1290.94,722.05) 1312.6,743.7 1312.6,762 1357.85,807.26 1357.85,998.6 1386.02,1026.77 1386.02,1088.78 1376.38,1098.43 1344.88,1098.43 v1@1326.77,1116.54
  Bottom Layer w7.87: v2(1468.5,279.53) HDR_B1.23@1468.5,338.58
IO9: HDR_B1.25 U4.AC9 | length 1012.3
  Top Layer w5: v1(1326.77,1078.74) U4.AC9@1346.46,1098.42 ; v1(1337.21,888.98) 1313,864.78 1313,720.47 1313,716.79 1280.71,684.5 1280.71,672.05 1280.71,530.32 1500,311.02 v2(1500,279.53)
  MidLayer3 w5: v1(1326.77,1078.74) 1346.46,1059.05 1346.46,898.23 v1(1337.21,888.98)
  Bottom Layer w7.87: v2(1500,279.53) HDR_B1.25@1500,338.58
IO10: HDR_B1.27 U4.AA10 | length 1436.4
  Top Layer w5: v1(1366.14,1157.48) U4.AA10@1385.83,1177.17
  MidLayer2 w5: v1(1366.14,1157.48) 1385.83,1137.8 1385.83,906.94 1478.01,814.75 1572.43,814.75 1616.71,770.47 1699.53,770.47 1714,756 1791.68,756 1832.68,715 1832.68,683.86 1837.8,678.74 1837.8,585.82 v2(1531.5,279.53)
  Bottom Layer w7.87: v2(1531.5,279.53) HDR_B1.27@1531.5,338.58
IO11: HDR_B1.29 U4.AE10 | length 954.6
  Top Layer w5: U4.AE10@1385.83,1019.68 1368,1001.86 1368,949 1371.7,945.3 1371.7,767.72 1371.7,759.35 1340.43,728.09 1340.18,728.09 1290.71,678.62 1290.71,678.36 1290.71,583.31 1330.71,543.31 1562.99,311.02 v2(1562.99,279.53)
  Bottom Layer w7.87: v2(1562.99,279.53) HDR_B1.29@1562.99,338.58
IO12: HDR_B1.31 U4.AF10 | length 924.8
  Top Layer w5: U4.AF10@1385.83,980.31 1385,979.49 1385,957 1417.05,924.95 1417.05,812.74 1385,780.7 1385,758.51 1337.35,710.86 1337.09,710.86 1323.21,696.97 1323.21,680.73 1330.71,673.23 1330.71,574.8 1354.33,551.18 1594.49,311.02 v2(1594.49,279.53)
  Bottom Layer w7.87: v2(1594.49,279.53) HDR_B1.31@1594.49,338.58
IO13: HDR_B1.33 U4.AC11 | length 1096
  Top Layer w5: v1(1403.94,732.28) 1381.89,732.28 1361.83,712.22 1361.83,681.1 1361.83,680.98 1354.33,673.48 1354.33,582.68 1393.7,543.31 1625.99,311.02 v2(1625.99,279.53) ; v1(1405.51,1078.74) U4.AC11@1425.2,1098.42
  MidLayer3 w5: v1(1403.94,732.28) 1385.37,748.24 1385.37,784.37 1401,800 1415,800 1452,837 1452,999.2 1425.2,1026 1425.2,1033.2 1426,1034 ; v1(1405.51,1078.74) 1405.51,1067.72 1425.2,1048.03 1425.2,1034
  Bottom Layer w7.87: v2(1625.99,279.53) HDR_B1.33@1625.99,338.58
IO14: HDR_B1.35 U4.AC12 | length 1062.5
  Top Layer w5: v1(1406,773) 1429.13,744.09 1429.13,730.17 1411.56,712.6 1401.83,712.6 1386.2,696.97 1386.2,680.48 1393.7,672.98 1393.7,574.8 1417.32,551.18 1657.48,311.02 v2(1657.48,279.53) ; v1(1444.88,1078.74) U4.AC12@1464.57,1098.42
  MidLayer3 w5: v1(1406,773) 1464.57,831.57 1464.57,1049.61 1444.88,1069.29 v1(1444.88,1078.74)
  Bottom Layer w7.87: v2(1657.48,279.53) HDR_B1.35@1657.48,338.58
IO15: HDR_B1.37 U4.AE12 | length 940.5
  Top Layer w5: U4.AE12@1464.92,1019.37 1445.35,999.8 1445.35,969.61 1456.69,958.27 1456.69,764.17 1440.15,747.63 1440.15,723.61 1425.2,708.66 1425.2,681.1 1417.32,673.23 1417.32,582.68 1456.69,543.31 1688.98,311.02 v2(1688.98,279.53)
  Bottom Layer w7.87: v2(1688.98,279.53) HDR_B1.37@1688.98,338.58
IO16: HDR_B1.39 U4.W13 | length 1141.4
  Top Layer w5: v1(1484.25,1236.22) U4.W13@1503.94,1255.91
  MidLayer1 w5: v1(1484.25,1236.22) 1484.25,1235.04 1505.94,1213.36 1520.87,1198.43 1520.87,891.95 1688.58,724.23 1688.58,311.42 v2(1720.47,279.53)
  Bottom Layer w7.87: v2(1720.47,279.53) HDR_B1.39@1720.47,338.58
IO17: HDR_B1.41 U4.AE13 | length 956.4
  Top Layer w5: 1483.98,998.39 1483.98,760.9 1490.16,754.72 1490.16,728.2 1470.24,708.29 1460.51,708.29 1449.19,696.97 1449.19,680.73 1456.69,673.23 1456.69,606.3 1519.68,543.31 1751.97,311.02 v2(1751.97,279.53) ; 1484.49,999.17 U4.AE13@1504.17,1018.86
  Bottom Layer w7.87: v2(1751.97,279.53) HDR_B1.41@1751.97,338.58
IO18: HDR_B1.43 U4.AE14 | length 1020.3
  Top Layer w5: U4.AE14@1543.31,1019.68 1523.23,999.61 1523.23,836.76 1574.82,785.16 1574.82,769.17 1563.51,757.85 1517.95,757.85 1500.27,740.18 1500.27,692.93 1480.31,672.98 1480.31,602.36 1783.47,299.21 v2(1783.47,279.53)
  Bottom Layer w7.87: v2(1783.47,279.53) HDR_B1.43@1783.47,338.58
IO19: HDR_B1.45 U4.AF14 | length 936.5
  Top Layer w5: U4.AF14@1543.31,980.31 1543.31,940.94 1543.31,830.82 1572.89,801.24 1584.82,789.31 1584.82,765.02 1548.14,728.35 1543.31,728.35 1527.56,712.6 1512.18,697.22 1512.18,680.48 1519.31,673.35 1519.31,594.86 1814.96,299.21 v2(1814.96,279.53)
  MidLayer2 w5: v2@1814.57,278.35 v2@1815.35,279.13
  Bottom Layer w7.87: v2(1814.96,279.53) HDR_B1.45@1814.96,338.58
IO20: HDR_B1.47 U4.AB15 | length 1215.8
  Top Layer w5: U4.AB15@1582.68,1137.8 v1(1602.36,1118.11) ; v1(1616.54,919.29) 1616.54,768.06 1553.54,705.07 1553.54,683.46 1540.94,670.87 1540.94,616.54 1661.58,495.9 1835.04,322.44 1835.04,255.12 v2(1814.17,234.25)
  MidLayer3 w5: v1@1602.36,1117.32 1622.05,1097.64 1622.05,1051.18 1640.16,1033.07 1640.16,942.91 v1(1616.54,919.29)
  Bottom Layer w7.87: v2(1814.17,234.25) 1846.46,266.54 HDR_B1.47@1846.46,338.58
IO21: HDR_B1.49 U4.V15 | length 1394.9
  Top Layer w5: U4.V15@1582.68,1295.28 v1(1602.36,1275.59)
  MidLayer2 w5: v1(1602.36,1275.59) 1602.36,1263.78 1622.05,1244.1 1622.05,1045.99 1950.79,717.25 1950.79,683.07 1964.57,669.29 1964.57,649.21 1932.76,617.4 1932.76,278.82 1887.8,233.86 v2(1857.48,233.86)
  Bottom Layer w7.87: v2(1857.48,233.86) 1867.72,244.09 1867.72,289.76 1877.95,300 HDR_B1.49@1877.95,338.58
IO22: HDR_B1.51 U4.U15 | length 1309.7
  Top Layer w5: U4.U15@1583.09,1334.08 1583.24,1334.08 v1(1602.36,1314.96)
  MidLayer2 w5: v1(1602.36,1314.96) 1600,1314.96 1582.48,1297.44 1582.48,993 1594.48,981 1653,981 1888.2,745.8 1888.2,682.67 1900,670.87 1900,288.98 v2(1889.76,279.53)
  Bottom Layer w7.87: v2(1889.76,279.53) 1909.45,299.21 HDR_B1.51@1909.45,338.58
IO23: HDR_B1.53 U4.AF18 | length 1015.2
  Top Layer w5: U4.AF18@1700.79,980.31 1700.79,938.74 1713.78,925.74 1713.78,794.49 1746.21,762.06 1746.21,683.85 1775.34,654.72 1775.34,407.73 1856.51,326.56 1856.51,268.69 1894.88,230.32 v2(1894.88,201.57)
  Bottom Layer w7.87: v2(1894.88,201.57) 1894.88,233.86 1940.95,279.92 HDR_B1.53@1940.95,338.58
IO24: HDR_B1.55 U4.Y17 | length 1182.4
  Top Layer w5: U4.Y17@1661.42,1216.54 v1(1681.1,1196.85)
  MidLayer2 w5: v1(1681.1,1196.85) 1700.79,1177.16 1700.79,1003.21 1973.68,730.32 1988.98,730.32 2009.45,709.84 2009.45,687.4 2031.1,665.75 2031.1,627.56 1972.44,568.9 v2(1972.44,279.53)
  Bottom Layer w7.87: v2(1972.44,279.53) HDR_B1.55@1972.44,338.58
IO25: HDR_B1.57 U4.U18 | length 1517.3
  Top Layer w5: U4.U18@1700.79,1334.65 v1(1720.47,1314.96)
  MidLayer2 w5: v1(1720.47,1314.96) 1740.53,1335.02 1771.69,1335.02 1779.15,1327.56 1779.15,1147.26 1769.68,1137.8 1750.01,1137.8 1744.76,1132.55 ; 1744.76,1132.55 1740.16,1127.95 1740.16,981.1 1972.44,748.82 2007.09,748.82 2057.48,698.43 2057.48,683.46 2046.06,672.05 2046.06,621.26 1992.52,567.72 1992.52,261.42 1969.88,238.78 v2@1969.29,238.19
  Bottom Layer w7.87: v2(1970.08,238.58) 2003.94,272.44 HDR_B1.57@2003.94,338.58
IO26: HDR_B1.59 U4.AD19 | length 1026
  Top Layer w5: U4.AD19@1740.16,1059.05 v1(1759.84,1039.37)
  MidLayer2 w5: v1(1759.84,1039.37) 1759.84,977.95 1975.59,762.2 2012.6,762.2 2074.8,700 2074.8,685.04 2088.58,671.26 2088.58,615.35 2035.04,561.81 v2@2035.04,280.32
  Bottom Layer w7.87: v2(2035.43,279.53) HDR_B1.59@2035.43,338.58
IO27: HDR_B1.61 U4.Y20 | length 1221.1
  Top Layer w5: U4.Y20@1779.53,1216.54 v1(1799.21,1196.85)
  MidLayer2 w5: v1@1798.42,1196.85 v1(1799.21,1196.85) 1799.21,1109.84 1779.53,1090.16 1779.53,1016.14 1825.59,970.08 1850,970.08 1889.08,931 1940,931 2118.56,752.44 2118.56,681.55 2107.87,670.87 2107.87,604.33 2098.99,595.45 2064.57,561.02 2064.57,281.89 v2(2066.93,279.53)
  Bottom Layer w7.87: v2(2066.93,279.53) HDR_B1.61@2066.93,338.58
IO28: HDR_B1.63 U4.W20 | length 1391.3
  Top Layer w5: U4.W20@1779.53,1255.91 v1(1799.21,1236.22)
  MidLayer2 w5: v1@1798.82,1236.22 v1(1799.21,1236.22) 1799.21,1235.43 1818.9,1215.75 1818.9,993.31 1831.89,980.32 1923.62,980.32 2135.43,768.5 2135.43,687.4 2151.18,671.65 2151.18,621.26 2141.36,611.44 2099.21,569.29 2099.21,263.39 v2(2066.14,230.32)
  Bottom Layer w7.87: v2(2066.14,230.32) 2098.43,262.6 2098.43,280.32 ; 2098.43,279.53 HDR_B1.63@2098.43,338.58
IO29: HDR_B1.65 U4.AD21 | length 1162.9
  Top Layer w5: U4.AD21@1818.9,1059.05 v1(1838.58,1039.37)
  MidLayer2 w5: v1(1838.58,1039.37) 1838.58,1030.71 1871.71,997.58 1924.9,997.58 1938.48,984 ; 1938.37,983.89 1943.17,979.08 1964.06,979.08 1992.6,1007.62 2075.26,1007.62 2145.12,937.75 2145.12,862.97 2186.22,821.87 2186.22,686.22 2171.34,671.34 2171.34,320.94 v2(2129.92,279.53)
  Bottom Layer w7.87: v2(2129.92,279.53) HDR_B1.65@2129.92,338.58
IO30: HDR_B1.67 U4.Y21 | length 1328.2
  Top Layer w5: U4.Y21@1818.9,1216.54 v1(1838.58,1196.85)
  MidLayer2 w5: v1(1838.58,1196.85) 1858.27,1177.17 1858.27,1029.13 1867.72,1019.68 2080.9,1019.68 2225.81,874.78 2225.81,738 2199.24,711.43 2199.24,686.59 2213.78,672.05 2213.78,331.89 v2(2161.42,279.53)
  Bottom Layer w7.87: v2(2161.42,279.53) HDR_B1.67@2161.42,338.58
IO31: HDR_B1.69 U4.AE23 | length 937.6
  Top Layer w5: U4.AE23@1897.64,1019.68 1896.89,1019.68 1878.7,1001.5 1878.7,955.94 1892.35,942.3 1902.66,931.99 1902.66,750.34 1947,706 1947,687 1965,669 1965,507.44 v2(2192.91,279.53)
  Bottom Layer w7.87: v2(2192.91,279.53) HDR_B1.69@2192.91,338.58
IO32: HDR_B1.71 U4.AC23 | length 1103.9
  Top Layer w5: U4.AC23@1897.64,1098.42 v1(1917.32,1078.74)
  MidLayer2 w5: v1(1917.32,1078.74) 1937.01,1059.06 1964.96,1059.06 1981.1,1042.91 2077.17,1042.91 2246.06,874.02 2246.06,683.07 2224.41,661.42 v2(2224.41,279.53)
  Bottom Layer w7.87: v2(2224.41,279.53) HDR_B1.71@2224.41,338.58
IO33: HDR_B1.73 U4.AB23 | length 1323.8
  Top Layer w5: U4.AB23@1897.64,1137.8 v1(1917.32,1118.11)
  MidLayer2 w5: v1(1917.32,1118.11) 1937.01,1098.43 2040.11,1098.43 2042.78,1101.1 2122.1,1101.1 2322.83,900.36 2322.83,688.98 2341.73,670.08 2341.73,635.83 2307.87,601.97 2307.87,258.66 v2(2291.34,242.13)
  Bottom Layer w7.87: HDR_B1.73@2255.91,338.58 2255.91,277.56 v2(2291.34,242.13)
IO34: HDR_B1.75 U4.AC24 | length 1099.6
  Top Layer w5: U4.AC24@1937.01,1098.42 v1(1956.69,1078.74)
  MidLayer2 w5: v1(1956.69,1078.74) 1966.54,1078.74 1992.13,1053.15 2084.25,1053.15 2309.06,828.35 2309.06,683.07 2288.19,662.21 v2(2288.19,280.31)
  Bottom Layer w7.87: v2@2287.4,279.53 2287.4,280.31 HDR_B1.75@2287.4,338.58
IO35: HDR_B1.77 U4.AF25 | length 912.1
  Top Layer w5: U4.AF25@1976.38,980.31 1976.38,929.53 2131.1,774.8 2131.1,691.73 2318.9,503.93 2318.9,288.97 v2(2329.13,278.74)
  Bottom Layer w7.87: HDR_B1.77@2318.9,338.58 2318.9,288.97 v2(2329.13,278.74) ; v2@2330.51,280.12 v2@2330.71,279.92
KBCLOCK: HDR_T1.26 U4.E15 | length 1201.8
  Top Layer w5: v1(1563.78,1827.56) 1582.68,1808.66 U4.E15@1582.68,1807.09
  MidLayer4 w5: 1383.27,2242.32 1582.68,2042.91 1582.68,1846.46 v1(1563.78,1827.56) ; 1383.46,2242.52 1383.46,2260.63 1394.88,2272.04 1394.88,2353.93 1401.97,2361.02 1401.97,2668.5 ; 1401.97,2668.9 1401.97,2668.5 ; v1(1467.72,2734.25) 1401.97,2668.5
  Bottom Layer w5: v1(1467.72,2734.25) 1500,2701.97 HDR_T1.26@1500,2606.3
KBDATA: HDR_T1.28 U4.F15 | length 1465.6
  Top Layer w5: U4.F15@1582.68,1767.72 v1(1602.36,1787.4)
  MidLayer4 w5: v1(1482.28,2781.1) 1366.2,2665.02 1366.2,2397.7 1290.16,2321.65 1290.16,2272.83 1329.13,2233.86 1366.54,2233.86 1535.23,2065.16 1542.91,2057.48 1542.91,1819.29 1555.12,1807.09 1583.86,1807.09 1602.36,1788.58 v1(1602.36,1787.4)
  Bottom Layer w5: v1(1482.28,2781.1) 1530.71,2732.68 1530.71,2606.3 HDR_T1.28@1530.71,2604.72
LED0: HDR_B1.6 U4.AB7 | length 565.7
  Top Layer w5: v1(1248.03,1118.11) U4.AB7@1267.72,1137.8
  MidLayer1 w5: v2(1185.04,665.35) 1192.61,672.92 1192.61,977.74 1228.35,1013.47 1228.35,1098.43 v1(1248.03,1118.11)
  Bottom Layer w7.87: HDR_B1.6@1185.04,606.3 v2(1185.04,665.35)
LED1: HDR_B1.8 U4.AD7 | length 481.5
  Top Layer w5: v1(1248.03,1039.37) U4.AD7@1267.72,1059.05
  MidLayer1 w5: v2(1216.54,688.98) 1207.45,698.06 1207.45,964.82 1247.64,1005 1247.64,1038.98 v1(1248.03,1039.37)
  Bottom Layer w7.87: HDR_B1.8@1216.54,606.3 v2(1216.54,688.98)
LED2: HDR_B1.10 U4.AE8 | length 454.4
  Top Layer w5: v1(1269.29,913.78) 1288.54,933.03 1288.54,999.69 1306.42,1017.56 1307.09,1017.56 U4.AE8@1307.2,1017.56
  MidLayer1 w5: v2(1248.03,665.35) 1248.03,695.67 1231.41,712.29 1231.41,883.41 1261.78,913.78 v1(1269.29,913.78)
  Bottom Layer w7.87: HDR_B1.10@1248.03,606.3 v2(1248.03,665.35)
LED3: HDR_B1.12 U4.AF8 | length 407.6
  Top Layer w5: v1(1251,750) 1263.46,762.46 1263.46,879.7 1292.98,909.22 ; 1293.1,909.1 1308.74,924.74 U4.AF8@1308.74,978.15
  Bottom Layer w7.87: v1(1251,750) 1251,710 1273,688 1279.53,681.43 HDR_B1.12@1279.53,606.3
LED4: HDR_B1.14 U4.Y10 | length 702.6
  Top Layer w5: v1(1366.14,1196.85) U4.Y10@1385.83,1216.54
  MidLayer1 w5: v2(1311.02,665.35) 1312.6,666.93 1312.6,1020.8 1307.09,1026.31 1307.09,1207.48 1309.42,1209.81 1315.77,1216.16 1346.83,1216.16 v1(1366.14,1196.85)
  Bottom Layer w7.87: HDR_B1.14@1311.02,606.3 v2(1311.02,665.35)
LED5: HDR_B1.16 U4.V11 | length 801.6
  Top Layer w5: U4.V11@1425.2,1295.28 1425.98,1295.28 v1(1444.88,1314.17)
  MidLayer1 w5: v2(1342.52,688.98) 1360,706.46 1360,1007.62 1346.83,1020.79 1346.83,1169.66 1354.33,1177.17 1376.38,1177.17 1385.45,1186.24 1385.45,1254.74 1395.91,1265.2 v1(1444.88,1314.17)
  Bottom Layer w7.87: HDR_B1.16@1342.52,606.3 v2(1342.52,688.98)
LED6: HDR_B1.18 U4.V12 | length 736.6
  Top Layer w5: v1(1444.88,1275.59) U4.V12@1464.57,1295.28
  MidLayer1 w5: v2(1374.02,665.35) 1374.02,1010.94 1385.45,1022.38 1385.45,1165.77 1396.47,1176.79 1413.78,1176.79 1425.57,1188.58 1425.57,1256.28 v1(1444.88,1275.59)
  Bottom Layer w7.87: HDR_B1.18@1374.02,606.3 v2(1374.02,665.35)
LED7: HDR_B1.20 U4.Y12 | length 657.4
  Top Layer w5: v1(1444.88,1196.85) U4.Y12@1464.57,1216.54
  MidLayer1 w5: v2(1405.51,688.98) 1405.51,689.51 1429,713 1429,746.99 1453,771.02 1453,997.57 1425.57,1025 1425.57,1166.51 1444.88,1185.83 v1(1444.88,1196.85)
  Bottom Layer w7.87: HDR_B1.20@1405.51,606.3 v2(1405.51,688.98)
LED_PGM: LED1.2 U2.4 | length 220.7
  Top Layer w7.87: LED1.2@1295.28,165.35 1301.18,165.35 1425.2,165.35 v1(1468.5,122.05)
  Bottom Layer w7.87: U2.4@1438.97,122.05 v1(1468.5,122.05)
LED_PWR: LED2.1 R2.2 | length 102.8
  Top Layer w15.75: v1(1893.7,169.29) LED2.1@1935.04,169.29 LED2.1@1937.01,169.29
  Bottom Layer w15.75: v1(1893.7,169.29) R2.2@1953.23,169.29
LX: L1.1 U6.1 U6.3 U6.14 U6.16 | length 321.6
  Top Layer w15.75: U6.16@2592.58,1633.25 2660.81,1633.25 2665.36,1637.8 v3@2669.29,1641.73 ; U6.14@2592.58,1683.25 2651.4,1683.25 ; 2653.54,1681.1 2651.4,1683.25 ; v3@2669.29,1677.16 2663.21,1683.25 2661.42,1683.25 2651.4,1683.25 ; 2748.03,1641.73 2756.52,1633.25 U6.1@2824.58,1633.25 ; 2748.03,1677.17 2754.11,1683.25 U6.3@2824.58,1683.25
  other v3: 2661.42,1641.73 2690.96,1641.73 2720.5,1641.73 2661.42,1669.29 2690.96,1669.29 2720.5,1669.29 2661.42,1696.85 2690.96,1696.85 2720.5,1696.85
MOUSECLOCK: HDR_T1.30 U4.E17 | length 1085.8
  Top Layer w5: U4.E17@1661.42,1807.09 v1(1681.1,1826.77)
  MidLayer4 w5: v2(1562.99,2665.35) 1522.83,2625.2 1522.83,2274.8 1511.02,2262.99 1511.02,2182.68 1666.93,2026.77 1666.93,1977.56 1653.94,1964.57 1631.89,1964.57 1622.05,1954.72 1622.05,1857.48 1633.07,1846.46 1664.17,1846.46 1681.1,1829.53 v1(1681.1,1826.77)
  Bottom Layer w7.87: HDR_T1.30@1562.99,2606.3 v2(1562.99,2665.35)
MOUSEDATA: HDR_T1.32 U4.C17 | length 990.2
  Top Layer w5: U4.C17@1661.42,1885.83 v1(1681.1,1905.51)
  MidLayer4 w5: v2@1594.49,2690.94 v2(1594.49,2688.98) 1594.49,2660.63 1542.52,2608.66 1542.52,2272.44 1555.91,2259.06 1555.91,2160.24 1679.92,2036.22 1679.92,1972.44 1661.42,1953.94 1661.42,1925.2 v1(1681.1,1905.51)
  Bottom Layer w7.87: HDR_T1.32@1594.49,2606.3 v2(1594.49,2688.98)
NetC120_1: C120.1 U7.6 | length 96.1
  Top Layer w5: U7.6@1940.94,2496.06 1972.44,2496.06 1996.06,2519.68 1996.06,2538.38 1991.14,2543.3 C120.1@1987.2,2547.24
NetLED1_1: LED1.1 R1.2 | length 87.1
  Top Layer w7.87: v1(1181.1,169.29) LED1.1@1222.44,169.29
  Bottom Layer w7.87: v1(1181.1,169.29) R1.2@1226.85,169.29
NetR9_1: R9.1 U5.4 | length 74.9
  Bottom Layer w5: R9.1@736.03,2769.44 759.18,2769.44 766.54,2762.09 U5.4@807.86,2762.09
NetR21_2: R21.2 R22.1 | length 60
  Top Layer w13.78: R21.2@2910.94,1866.14 R22.1@2970.94,1866.14
NetRN1_8: RN1.8 RN4.5 | length 91.3
  Bottom Layer w5: RN1.8@1688.58,3271.65 RN4.5@1779.53,3271.65 RN4.5@1779.92,3271.65
NetRN2_8: RN2.8 RN6.5 | length 91.3
  Bottom Layer w5: RN2.8@1393.3,3271.65 RN6.5@1483.28,3271.65 RN6.5@1484.64,3271.65
NEXUS_TCK: HDR_T1.82 U4.A14 | length 2624.1
  Top Layer w5: U4.A14@1543.31,1964.57 v1(1562.99,1984.25)
  MidLayer3 w5: v1(1562.99,1984.25) 1582.68,1964.57 1582.68,1917.32 1543.31,1877.95 1543.31,1506.16 1568.52,1480.94 1881.26,1480.94 1897.22,1464.98 1897.22,1426.65 1908.54,1415.33 1924.53,1415.33 1935.85,1426.65 1935.85,1441.11 1959.72,1464.98 2150.02,1464.98 2287.4,1602.36 2287.4,2059.11 2433.07,2204.78 2433.07,2263.78 2425.2,2271.65 2425.2,2381.89 2381.89,2425.2 v2(2381.89,2665.35)
  Bottom Layer w7.87: HDR_T1.82@2381.89,2606.3 v2(2381.89,2665.35)
NEXUS_TDI: HDR_T1.84 U4.R18 | length 1969.7
  Top Layer w5: U4.R18@1700.79,1413.39 v1(1720.47,1393.7)
  MidLayer3 w5: v1(1720.47,1393.7) 1737.35,1376.82 1740.18,1374 1748.41,1374 ; 1748.42,1374.01 1758.66,1374.02 1884.25,1374.02 1910.24,1400 1950,1400 2001.97,1451.97 2151.15,1451.97 2299.21,1600.03 2299.21,2056.04 2444.88,2201.71 2444.88,2251.97 2464.57,2271.65 2464.57,2377.95 2413.38,2429.13 v2(2413.38,2688.98)
  Bottom Layer w7.87: HDR_T1.84@2413.39,2606.3 v2(2413.38,2688.98)
NEXUS_TDO: HDR_T1.76 U4.D24 | length 1093.3
  Top Layer w5: U4.D24@1937.01,1846.46 v1(1956.69,1866.14) ; v1@1957.79,1865.98 v1@1957.79,1866.14 ; v1(2080.71,2214.28) 2074.8,2220.19 2074.8,2259.84 2086.61,2271.65 2287.4,2472.44 v2(2287.4,2688.98)
  MidLayer1 w5: v1(1956.69,1866.14) 1956.76,1866.14 1956.76,1867.01 1937.3,1886.47 1937.3,1917.2 1955.42,1935.33 1955.42,1952.27 2064.52,2061.37 2064.52,2198.08 v1@2080.21,2213.78 ; v1@2080.71,2213.78 v1@2080.46,2214.03 ; v1@2080.21,2213.78 v1@2080.46,2214.03 ; v1@2080.21,2213.78 v1@2080.21,2214.28 ; v1@2080.21,2214.28 v1(2080.71,2214.28) v1@2080.46,2214.03 ; v1@2080.21,2214.28 v1@2080.46,2214.03
  Bottom Layer w7.87: HDR_T1.76@2287.4,2606.3 v2(2287.4,2688.98)
NEXUS_TMS: HDR_T1.80 U4.P23 | length 1707.5
  Top Layer w5: U4.P23@1897.64,1452.76 v1(1916.54,1434.65)
  MidLayer3 w5: v1(1916.54,1434.65) 1916.54,1455.91 1937.52,1476.89 2146.18,1476.89 2275.59,1606.3 2275.59,2062.06 2393.7,2180.17 2393.7,2263.78 2401.57,2271.65 2401.57,2366.14 2350.39,2417.33 v2(2350.39,2688.98)
  Bottom Layer w7.87: HDR_T1.80@2350.4,2606.3 v2(2350.39,2688.98)
NFAULT: R24.2 U7.8 | length 239.6
  Top Layer w5: R24.2@1741.65,2637.79 1741.65,2593.35 1788.75,2546.25 U7.8@1917.32,2546.26
ONE_WIRE.PIO2: U1.6
ONE_WIRE_DB_PB: HDR_B1.79 U4.AC8 | length 1928.8
  Top Layer w5: v1(1287.4,1078.74) U4.AC8@1307.09,1098.42
  MidLayer3 w5: v1(1287.4,1078.74) 1287.4,1066.86 1267.34,1046.8 1267.34,995.76 1247.71,976.13 1247.71,809.71 1215.96,777.96 1215.96,724.99 1238.39,702.55 1255.06,685.88 1267.72,673.23 1267.72,622.05 1350.79,538.98 2107.78,538.98 2357.48,289.28 2357.48,275.47 2357.48,267.72 v2(2383.07,242.13)
  Bottom Layer w5: HDR_B1.79@2351.57,337.01 2351.57,273.62 v2(2383.07,242.13)
ONE_WIRE_DBID: HDR_T1.92 U1.2 | length 314.2
  Bottom Layer w5: HDR_T1.92@2539.37,2606.3 2539.37,2663.36 2546.59,2670.58 2546.59,2812.34 2580.71,2846.46 U1.2@2637.59,2846.45
ONE_WIRE_PIO1: HDR_T1.91 U1.3 | length 1165.6
  MidLayer4 w5: v1(2539.36,2248.03) 2587.39,2200 v1(2615,2200)
  Bottom Layer w5: v1(2539.36,2248.03) HDR_T1.91@2539.36,2318.89 ; v1(2615,2200) 2755.12,2200 2787.4,2232.28 2787.4,2562.4 2811.02,2586.02 2811.02,2716.53 2795.27,2732.28 2732.28,2732.28 2708.66,2755.9 2708.66,2877.95 2690.15,2896.45 U1.3@2637.59,2896.45
PROG_B: R7.2 U4.A2 | length 546.2
  Top Layer w5: v1@661.39,2174.5 v1(658.6,2174.5) 848.61,1984.49 1009.17,1984.49 1009.29,1984.37 1051.02,1984.37 1070.85,1964.55 1071.38,1964.02 U4.A2@1071.65,1964.02
  Bottom Layer w5: v1(658.6,2174.5) 687.58,2145.52 R7.2@689.74,2145.52
REF_1V2: C117.2 U6.10 | length 86.8
  Top Layer w15.75: C117.2@2505.9,1783.46 2506.11,1783.25 U6.10@2592.58,1783.25
REF_CLK: HDR_B1.4 U4.Y14 | length 1141.2
  Top Layer w5: v1(1523.62,736.22) 1525.05,737.65 v1@1524.66,737.65 ; U4.Y14@1543.31,1216.54 v1(1562.99,1196.85)
  MidLayer1 w5: v2(1153.54,688.98) 1153.54,665.35 1177.17,641.73 1511.81,641.73 1551.18,681.1 1551.18,708.66 v1(1523.62,736.22)
  MidLayer2 w5: v1@1562.2,1197.64 1562.6,1198.03 v1@1562.99,1198.03
  MidLayer3 w5: v1(1523.62,736.22) 1541.88,736.22 1574.82,769.17 1574.82,791.32 1543.68,822.46 1543.68,1177.54 v1(1562.99,1196.85)
  Bottom Layer w7.87: HDR_B1.4@1153.54,606.3 v2(1153.54,688.98)
RS232_CTS: HDR_T1.22 U4.A15 | length 859
  Top Layer w5: U4.A15@1582.68,1964.57 v1(1602.36,1984.25)
  MidLayer4 w5: v2(1437.01,2665.35) 1437.01,2361.02 1409.84,2333.86 1409.84,2276.77 1432.28,2254.33 1432.28,2215.36 1602.36,2045.28 v1(1602.36,1984.25)
  Bottom Layer w7.87: HDR_T1.22@1437.01,2606.3 v2(1437.01,2665.35)
RS232_RTS: HDR_T1.18 U4.E12 | length 1536.8
  Top Layer w5: v1(1444.88,1826.77) U4.E12@1464.57,1807.09
  MidLayer4 w5: v1(1391.34,2782.28) 1358.66,2749.61 1241.83,2749.61 1160.24,2668.01 1160.24,2276.77 1179.92,2257.09 1179.92,2225.2 1298.43,2106.69 1425.98,2106.69 1464.57,2068.11 1464.57,1845.67 v1@1446.46,1827.56
  Bottom Layer w5: HDR_T1.18@1374.41,2607.48 1374.41,2765.35 v1(1391.34,2782.28)
RS232_RX: HDR_T1.24 U4.B15 | length 883.6
  Top Layer w5: U4.B15@1582.68,1925.2 v1(1602.36,1944.88)
  MidLayer4 w5: v1(1468.11,2665.75) 1468.11,2283.86 1491.49,2260.48 1491.49,2181.74 1622.05,2051.18 1622.05,1968.9 1602.36,1949.21 v1(1602.36,1944.88)
  Bottom Layer w5: HDR_T1.24@1467.72,2618.5 HDR_T1.24@1467.72,2623.62 ; HDR_T1.24@1468.11,2607.87 v1(1468.11,2665.75)
RS232_TX: HDR_T1.20 U4.G13 | length 1640.3
  Top Layer w5: v1(1484.25,1748.03) U4.G13@1503.94,1728.35
  MidLayer4 w5: v1(1435.04,2782.68) 1385.83,2733.46 1259.06,2733.46 1208.27,2682.68 1208.27,2275.19 1190.94,2257.87 1190.94,2231.5 1229.5,2192.94 1362.6,2192.94 1504.72,2050.82 1504.72,1771.65 1483.86,1750.79 v1@1483.86,1749.61
  Bottom Layer w5: HDR_T1.20@1405.51,2607.48 1405.51,2753.15 v1(1435.04,2782.68)
SCL: HDR_B1.5 U4.W7 | length 1106.8
  Top Layer w5: v1(1248.03,1236.22) U4.W7@1267.72,1255.91
  MidLayer3 w5: v2(1185.04,279.53) 1204.72,299.21 1204.72,673.23 1195.28,682.68 1195.28,952.07 1228.35,985.14 1228.35,1049.26 1237.87,1058.78 1260.5,1058.78 1267.39,1065.67 1267.39,1216.86 v1(1248.03,1236.22)
  Bottom Layer w7.87: v2(1185.04,279.53) HDR_B1.5@1185.04,338.58
SDA: HDR_B1.3 U4.AF4 | length 781
  Top Layer w5: U4.AF4@1149.61,980.31 1149.61,924.67 v1(1170.96,903.31)
  MidLayer3 w5: v2(1153.54,279.53) 1153.54,661.42 1177.17,685.04 1177.17,897.11 v1(1170.96,903.31)
  Bottom Layer w7.87: v2(1153.54,279.53) HDR_B1.3@1153.54,338.58
SLEEP_N: HDR_T1.93 U5.2 | length 2444
  MidLayer3 w5: v1(2526.91,2713.87) 2543.64,2697.14 2543.64,2638.1 2561.35,2620.39 2561.35,2240.57 2540.08,2219.29 v1(2539.37,2219.29)
  Bottom Layer w5: U5.2@922.01,2799.48 1044.02,2799.48 1128.65,2884.1 1563.58,2884.1 1658.04,2978.57 2032.94,2978.57 2161.85,2849.66 2232.7,2849.66 2332.08,2750.28 2490.5,2750.28 v1(2526.91,2713.87) ; v1@2537.8,2215.35 2570.87,2248.43 HDR_T1.93@2570.87,2338.58
SPI_CLK: HDR_T1.46 U4.D13 | length 1033.2
  Top Layer w5: v1(1484.25,1866.14) U4.D13@1503.94,1846.46
  MidLayer2 w5: v1(1484.25,1866.14) 1512.6,1894.49 1512.6,2201.4 1553.14,2241.94 1553.14,2261.83 1540.94,2274.02 1540.94,2391.34 1608.16,2458.56 v2(1814.96,2665.35)
  Bottom Layer w7.87: HDR_T1.46@1814.96,2606.3 v2(1814.96,2665.35)
SPI_DIN: HDR_T1.44 U4.A12 | length 955.5
  Top Layer w5: v1(1444.88,1984.25) U4.A12@1464.57,1964.57
  MidLayer2 w5: v1(1444.88,1984.25) 1444.88,2001.57 1478.16,2034.85 1478.16,2230.13 1519.38,2271.35 1519.38,2424.9 v2(1783.46,2688.98)
  Bottom Layer w7.87: HDR_T1.44@1783.47,2606.3 v2(1783.46,2688.98)
SPI_DOUT: HDR_T1.50 U4.E14 | length 1235.4
  Top Layer w5: U4.E14@1543.31,1807.09 1543.31,1806.3 v1(1562.99,1786.61)
  MidLayer2 w5: v1(1562.99,1786.61) 1537.01,1812.6 1537.01,2173.66 1595.93,2232.57 1795.57,2232.57 1877.95,2314.95 v2(1877.95,2665.35)
  Bottom Layer w7.87: HDR_T1.50@1877.95,2606.3 v2(1877.95,2665.35)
